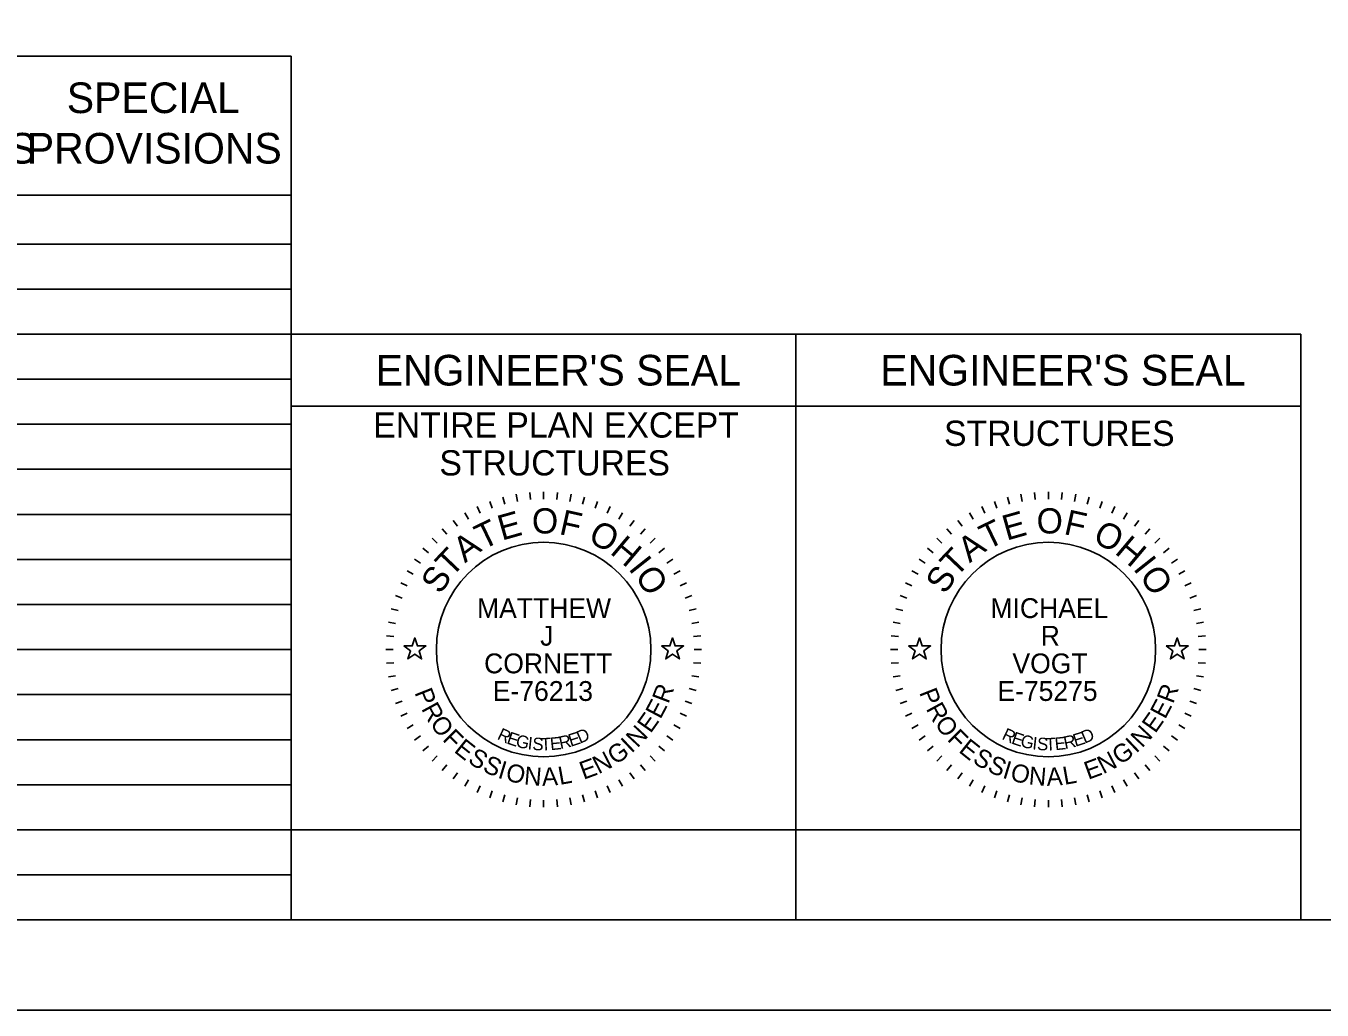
# Model space of a CAD drawing. Extents: x 0 to 34, y 0 to 22.
# Drawn here: x 22.13 to 29.32, y 0 to 5.46 of the extents above; entities that cross this region are included whole.
import ezdxf

# ---------------------------------------------------------------- set-up
doc = ezdxf.new("R2010")
doc.units = 0
for name, color, linetype in [('GM_X_State_Route', 7, 'Continuous'), ('SH_Border', 7, 'Continuous'), ('SH_Cut_Line', 7, 'Continuous'), ('SH_Data', 7, 'Continuous'), ('SH_Text', 7, 'Continuous')]:
    doc.layers.add(name, color=color, linetype=linetype)

msp = doc.modelspace()

# ---------------------------------------------------------------- linework, layer by layer
at = {"layer": 'GM_X_State_Route'}
for p, q in [((24.7007, 2.8222), (24.7144, 2.7846)), ((24.7735, 2.8452), (24.7839, 2.8065)), ((24.8481, 2.8617), (24.855, 2.8223)), ((24.9237, 2.8717), (24.9272, 2.8318)), ((25, 2.875), (25, 2.835)), ((25.0763, 2.8717), (25.0728, 2.8318)), ((25.1519, 2.8617), (25.145, 2.8223)), ((25.2265, 2.8452), (25.2161, 2.8065)), ((25.2993, 2.8222), (25.2856, 2.7846)), ((27.5007, 2.8222), (27.5144, 2.7846)), ((27.5735, 2.8452), (27.5839, 2.8065)), ((27.6481, 2.8617), (27.655, 2.8223)), ((27.7237, 2.8717), (27.7272, 2.8318)), ((27.8, 2.875), (27.8, 2.835)), ((27.8763, 2.8717), (27.8728, 2.8318)), ((27.9519, 2.8617), (27.945, 2.8223)), ((28.0265, 2.8452), (28.0161, 2.8065)), ((28.0993, 2.8222), (28.0856, 2.7846)), ((24.5625, 2.7578), (24.5825, 2.7231)), ((24.6302, 2.793), (24.6471, 2.7568)), ((25.3698, 2.793), (25.3529, 2.7568)), ((25.4375, 2.7578), (25.4175, 2.7231)), ((27.3625, 2.7578), (27.3825, 2.7231)), ((27.4302, 2.793), (27.4471, 2.7568)), ((28.1698, 2.793), (28.1529, 2.7568)), ((28.2375, 2.7578), (28.2175, 2.7231)), ((24.4376, 2.6703), (24.4633, 2.6396)), ((24.4981, 2.7168), (24.5211, 2.684)), ((25.5019, 2.7168), (25.4789, 2.684)), ((25.5624, 2.6703), (25.5367, 2.6396)), ((27.2376, 2.6703), (27.2633, 2.6396)), ((27.2981, 2.7168), (27.3211, 2.684)), ((28.3019, 2.7168), (28.2789, 2.684)), ((28.3624, 2.6703), (28.3367, 2.6396)), ((24.3813, 2.6187), (24.4096, 2.5904)), ((25.6187, 2.6187), (25.5904, 2.5904)), ((27.1813, 2.6187), (27.2096, 2.5904)), ((28.4187, 2.6187), (28.3904, 2.5904)), ((24.3297, 2.5624), (24.3604, 2.5367)), ((25.6703, 2.5624), (25.6396, 2.5367)), ((27.1297, 2.5624), (27.1604, 2.5367)), ((28.4703, 2.5624), (28.4396, 2.5367)), ((24.2832, 2.5019), (24.316, 2.4789)), ((25.7168, 2.5019), (25.684, 2.4789)), ((27.0832, 2.5019), (27.116, 2.4789)), ((28.5168, 2.5019), (28.484, 2.4789)), ((24.2422, 2.4375), (24.2769, 2.4175)), ((25.7578, 2.4375), (25.7231, 2.4175)), ((27.0422, 2.4375), (27.0769, 2.4175)), ((28.5578, 2.4375), (28.5231, 2.4175)), ((24.207, 2.3698), (24.2432, 2.3529)), ((25.793, 2.3698), (25.7568, 2.3529)), ((27.007, 2.3698), (27.0432, 2.3529)), ((28.593, 2.3698), (28.5568, 2.3529)), ((24.1778, 2.2993), (24.2154, 2.2856)), ((25.8222, 2.2993), (25.7846, 2.2856)), ((26.9778, 2.2993), (27.0154, 2.2856)), ((28.6222, 2.2993), (28.5846, 2.2856)), ((24.1548, 2.2265), (24.1935, 2.2161)), ((25.8452, 2.2265), (25.8065, 2.2161)), ((26.9548, 2.2265), (26.9935, 2.2161)), ((28.6452, 2.2265), (28.6065, 2.2161)), ((24.1383, 2.1519), (24.1777, 2.145)), ((25.8617, 2.1519), (25.8223, 2.145)), ((26.9383, 2.1519), (26.9777, 2.145)), ((28.6617, 2.1519), (28.6223, 2.145)), ((24.1283, 2.0763), (24.1682, 2.0728)), ((25.8717, 2.0763), (25.8318, 2.0728)), ((26.9283, 2.0763), (26.9682, 2.0728)), ((28.6717, 2.0763), (28.6318, 2.0728)), ((24.125, 2), (24.165, 2)), ((25.875, 2), (25.835, 2)), ((26.925, 2), (26.965, 2)), ((28.675, 2), (28.635, 2)), ((24.1283, 1.9237), (24.1682, 1.9272)), ((25.8717, 1.9237), (25.8318, 1.9272)), ((26.9283, 1.9237), (26.9682, 1.9272)), ((28.6717, 1.9237), (28.6318, 1.9272)), ((24.1383, 1.8481), (24.1777, 1.855)), ((25.8617, 1.8481), (25.8223, 1.855)), ((26.9383, 1.8481), (26.9777, 1.855)), ((28.6617, 1.8481), (28.6223, 1.855)), ((24.1548, 1.7735), (24.1935, 1.7839)), ((25.8452, 1.7735), (25.8065, 1.7839)), ((26.9548, 1.7735), (26.9935, 1.7839)), ((28.6452, 1.7735), (28.6065, 1.7839)), ((24.1778, 1.7007), (24.2154, 1.7144)), ((25.8222, 1.7007), (25.7846, 1.7144)), ((26.9778, 1.7007), (27.0154, 1.7144)), ((28.6222, 1.7007), (28.5846, 1.7144)), ((24.207, 1.6302), (24.2432, 1.6471)), ((24.2422, 1.5625), (24.2769, 1.5825)), ((25.7578, 1.5625), (25.7231, 1.5825)), ((25.793, 1.6302), (25.7568, 1.6471)), ((27.007, 1.6302), (27.0432, 1.6471)), ((27.0422, 1.5625), (27.0769, 1.5825)), ((28.5578, 1.5625), (28.5231, 1.5825)), ((28.593, 1.6302), (28.5568, 1.6471)), ((24.2832, 1.4981), (24.316, 1.5211)), ((25.7168, 1.4981), (25.684, 1.5211)), ((27.0832, 1.4981), (27.116, 1.5211)), ((28.5168, 1.4981), (28.484, 1.5211)), ((24.3297, 1.4376), (24.3604, 1.4633)), ((25.6703, 1.4376), (25.6396, 1.4633)), ((27.1297, 1.4376), (27.1604, 1.4633)), ((28.4703, 1.4376), (28.4396, 1.4633)), ((24.3813, 1.3813), (24.4096, 1.4096)), ((25.6187, 1.3813), (25.5904, 1.4096)), ((27.1813, 1.3813), (27.2096, 1.4096)), ((28.4187, 1.3813), (28.3904, 1.4096)), ((24.4376, 1.3297), (24.4633, 1.3604)), ((24.4981, 1.2832), (24.5211, 1.316)), ((25.5019, 1.2832), (25.4789, 1.316)), ((25.5624, 1.3297), (25.5367, 1.3604)), ((27.2376, 1.3297), (27.2633, 1.3604)), ((27.2981, 1.2832), (27.3211, 1.316)), ((28.3019, 1.2832), (28.2789, 1.316)), ((28.3624, 1.3297), (28.3367, 1.3604)), ((24.5625, 1.2422), (24.5825, 1.2769)), ((24.6302, 1.207), (24.6471, 1.2432)), ((25.3698, 1.207), (25.3529, 1.2432)), ((25.4375, 1.2422), (25.4175, 1.2769)), ((27.3625, 1.2422), (27.3825, 1.2769)), ((27.4302, 1.207), (27.4471, 1.2432)), ((28.1698, 1.207), (28.1529, 1.2432)), ((28.2375, 1.2422), (28.2175, 1.2769)), ((24.7007, 1.1778), (24.7144, 1.2154)), ((24.7735, 1.1548), (24.7839, 1.1935)), ((24.8481, 1.1383), (24.855, 1.1777)), ((24.9237, 1.1283), (24.9272, 1.1682)), ((25, 1.125), (25, 1.165)), ((25.0763, 1.1283), (25.0728, 1.1682)), ((25.1519, 1.1383), (25.145, 1.1777)), ((25.2265, 1.1548), (25.2161, 1.1935)), ((25.2993, 1.1778), (25.2856, 1.2154)), ((27.5007, 1.1778), (27.5144, 1.2154)), ((27.5735, 1.1548), (27.5839, 1.1935)), ((27.6481, 1.1383), (27.655, 1.1777)), ((27.7237, 1.1283), (27.7272, 1.1682)), ((27.8, 1.125), (27.8, 1.165)), ((27.8763, 1.1283), (27.8728, 1.1682)), ((27.9519, 1.1383), (27.945, 1.1777)), ((28.0265, 1.1548), (28.0161, 1.1935)), ((28.0993, 1.1778), (28.0856, 1.2154))]:
    msp.add_line(p, q, dxfattribs=at)
for points in [[(24.2236, 2.02), (24.2705, 2.02), (24.285, 2.0645), (24.2995, 2.02), (24.3464, 2.02), (24.3085, 1.9924), (24.323, 1.9478), (24.285, 1.9754), (24.247, 1.9478), (24.2615, 1.9924)], [(25.6536, 2.02), (25.7005, 2.02), (25.715, 2.0645), (25.7295, 2.02), (25.7764, 2.02), (25.7385, 1.9924), (25.753, 1.9478), (25.715, 1.9754), (25.677, 1.9478), (25.6915, 1.9924)], [(27.0236, 2.02), (27.0705, 2.02), (27.085, 2.0645), (27.0995, 2.02), (27.1464, 2.02), (27.1085, 1.9924), (27.123, 1.9478), (27.085, 1.9754), (27.047, 1.9478), (27.0615, 1.9924)], [(28.4536, 2.02), (28.5005, 2.02), (28.515, 2.0645), (28.5295, 2.02), (28.5764, 2.02), (28.5385, 1.9924), (28.553, 1.9478), (28.515, 1.9754), (28.477, 1.9478), (28.4915, 1.9924)]]:
    msp.add_lwpolyline(points, close=True, dxfattribs=at)
for centre in [(25, 2), (27.8, 2)]:
    msp.add_circle(centre, 0.595, dxfattribs=at)
at = {"layer": 'SH_Cut_Line'}
for p, q in [((10.15, 5.2918), (23.6, 5.2918)), ((23.6, 0.5), (23.6, 5.2918)), ((10.15, 4.5209), (23.6, 4.5209)), ((10.15, 4.25), (23.6, 4.25)), ((10.15, 4), (23.6, 4)), ((10.15, 3.75), (23.6, 3.75)), ((23.6, 0.5), (23.6, 3.75)), ((23.6, 3.75), (26.4, 3.75)), ((26.4, 0.5), (26.4, 3.75)), ((26.4, 0.5), (26.4, 3.75)), ((26.4, 3.75), (29.2, 3.75)), ((26.4, 3.75), (26.4, 0.5)), ((29.2, 3.75), (29.2, 0.5)), ((10.15, 3.5), (23.6, 3.5)), ((23.6, 3.35), (26.4, 3.35)), ((26.4, 3.35), (29.2, 3.35)), ((10.15, 3.25), (23.6, 3.25)), ((10.15, 3), (23.6, 3)), ((10.15, 2.75), (23.6, 2.75)), ((10.15, 2.5), (23.6, 2.5)), ((10.15, 2.25), (23.6, 2.25)), ((10.15, 2), (23.6, 2)), ((10.15, 1.75), (23.6, 1.75)), ((10.15, 1.5), (23.6, 1.5)), ((10.15, 1.25), (23.6, 1.25)), ((10.15, 1), (23.6, 1)), ((10.15, 0.75), (23.6, 0.75)), ((23.6, 0.5), (26.4, 0.5)), ((26.4, 0.5), (29.2, 0.5))]:
    msp.add_line(p, q, dxfattribs=at)
for points in [[(23.6, 0.5), (23.6, 1), (26.4, 1), (26.4, 0.5)], [(26.4, 0.5), (26.4, 1), (29.2, 1), (29.2, 0.5)]]:
    msp.add_lwpolyline(points, close=True, dxfattribs=at)
at = {"layer": 'SH_Data'}
msp.add_lwpolyline([(1.5, 21.5), (33.5, 21.5), (33.5, 0.5), (1.5, 0.5)], close=True, dxfattribs=at)
at = {"layer": 'SH_Text'}
msp.add_lwpolyline([(0, 0), (34, 0), (34, 22), (0, 22)], close=True, dxfattribs=at)

# ---------------------------------------------------------------- texts
at = {"layer": 'GM_X_State_Route'}
for s, height, rotation, p in [('E', 0.14, 15.75706, (24.7684, 2.6038)), ('O', 0.14, 359.78119, (24.9347, 2.6443)), ('F', 0.14, 347.43619, (25.0811, 2.6417)), ('E', 0.14, 15.75706, (27.5684, 2.6038)), ('O', 0.14, 359.78119, (27.7347, 2.6443)), ('F', 0.14, 347.43619, (27.8811, 2.6417)), ('T', 0.14, 25.71674, (24.6616, 2.5518)), ('O', 0.14, 332.25863, (25.2398, 2.6015)), ('T', 0.14, 25.71674, (27.4616, 2.5518)), ('O', 0.14, 332.25863, (28.0398, 2.6015)), ('A', 0.14, 36.47472, (24.5634, 2.4781)), ('H', 0.14, 319.91363, (25.3632, 2.5361)), ('A', 0.14, 36.47472, (27.3634, 2.4781)), ('H', 0.14, 319.91363, (28.1632, 2.5361)), ('T', 0.14, 46.4344, (24.4883, 2.3964)), ('I', 0.14, 308.36695, (25.4665, 2.4483)), ('T', 0.14, 46.4344, (27.2883, 2.3964)), ('I', 0.14, 308.36695, (28.2665, 2.4483)), ('S', 0.14, 57.19238, (24.4281, 2.3014)), ('O', 0.14, 303.14906, (25.5021, 2.4089)), ('S', 0.14, 57.19238, (27.2281, 2.3014)), ('O', 0.14, 303.14906, (28.3021, 2.4089)), ('R', 0.1, 69.23216, (25.6919, 1.6954)), ('R', 0.1, 69.23216, (28.4919, 1.6954)), ('P', 0.1, 291.49398, (24.2823, 1.7621)), ('E', 0.1, 61.99508, (25.6476, 1.6098)), ('P', 0.1, 291.49398, (27.0823, 1.7621)), ('E', 0.1, 61.99508, (28.4476, 1.6098)), ('R', 0.1, 298.73106, (24.319, 1.6717)), ('E', 0.1, 54.75801, (25.5933, 1.5314)), ('R', 0.1, 298.73106, (27.119, 1.6717)), ('E', 0.1, 54.75801, (28.3933, 1.5314)), ('O', 0.1, 306.46664, (24.3655, 1.5883)), ('O', 0.1, 306.46664, (27.1655, 1.5883)), ('F', 0.1, 314.7068, (24.4343, 1.4983)), ('R', 0.07, 334.48695, (24.7375, 1.5051)), ('E', 0.07, 341.03996, (24.7906, 1.4801)), ('G', 0.07, 347.47515, (24.8414, 1.4618)), ('I', 0.07, 353.78581, (24.9091, 1.4468)), ('S', 0.07, 356.89262, (24.9358, 1.4429)), ('T', 0.07, 3.00609, (24.9857, 1.4387)), ('E', 0.07, 6.01169, (25.0389, 1.4412)), ('R', 0.07, 11.91844, (25.0925, 1.4474)), ('E', 0.07, 17.68363, (25.1498, 1.4602)), ('D', 0.07, 23.30524, (25.201, 1.477)), ('I', 0.1, 43.28703, (25.4868, 1.4214)), ('N', 0.1, 47.02243, (25.5202, 1.4508)), ('F', 0.1, 314.7068, (27.2343, 1.4983)), ('R', 0.07, 334.48695, (27.5375, 1.5051)), ('E', 0.07, 341.03996, (27.5906, 1.4801)), ('G', 0.07, 347.47515, (27.6414, 1.4618)), ('I', 0.07, 353.78581, (27.7091, 1.4468)), ('S', 0.07, 356.89262, (27.7358, 1.4429)), ('T', 0.07, 3.00609, (27.7857, 1.4387)), ('E', 0.07, 6.01169, (27.8389, 1.4412)), ('R', 0.07, 11.91844, (27.8925, 1.4474)), ('E', 0.07, 17.68363, (27.9498, 1.4602)), ('D', 0.07, 23.30524, (28.001, 1.477)), ('I', 0.1, 43.28703, (28.2868, 1.4214)), ('N', 0.1, 47.02243, (28.3202, 1.4508)), ('E', 0.1, 321.43929, (24.4978, 1.4348)), ('S', 0.1, 328.67637, (24.5743, 1.3752)), ('G', 0.1, 35.04687, (25.3981, 1.357)), ('E', 0.1, 321.43929, (27.2978, 1.4348)), ('S', 0.1, 328.67637, (27.3743, 1.3752)), ('G', 0.1, 35.04687, (28.1981, 1.357)), ('S', 0.1, 335.91345, (24.6564, 1.3266)), ('I', 0.1, 343.15053, (24.7406, 1.2897)), ('O', 0.1, 346.88592, (24.7839, 1.2751)), ('E', 0.1, 20.07421, (25.2212, 1.277)), ('N', 0.1, 27.31129, (25.3045, 1.3075)), ('S', 0.1, 335.91345, (27.4564, 1.3266)), ('I', 0.1, 343.15053, (27.5406, 1.2897)), ('O', 0.1, 346.88592, (27.5839, 1.2751)), ('E', 0.1, 20.07421, (28.0212, 1.277)), ('N', 0.1, 27.31129, (28.1045, 1.3075)), ('N', 0.1, 355.12608, (24.8888, 1.2517)), ('A', 0.1, 2.86166, (24.9923, 1.2437)), ('L', 0.1, 10.09874, (25.0894, 1.249)), ('N', 0.1, 355.12608, (27.6888, 1.2517)), ('A', 0.1, 2.86166, (27.7923, 1.2437)), ('L', 0.1, 10.09874, (27.8894, 1.249))]:
    msp.add_text(s, height=height, rotation=rotation, dxfattribs=at).set_placement(p)
for s, p in [('MATTHEW', (24.6304, 2.1749)), ('MICHAEL', (27.4789, 2.1749)), ('J', (24.9808, 2.0216)), ('R', (27.7577, 2.0216)), ('CORNETT', (24.6696, 1.8684)), ('VOGT', (27.6009, 1.8684)), ('E-76213', (24.7177, 1.7151)), ('E-75275', (27.5173, 1.7151))]:
    msp.add_text(s, height=0.11, dxfattribs=at).set_placement(p)
at = {"layer": 'SH_Border'}
for s, p in [('SPECIAL', (22.3542, 4.9763)), ('SPECIFICATIONS', (20.2871, 4.6963)), ('PROVISIONS', (22.1323, 4.6963))]:
    msp.add_text(s, height=0.17, dxfattribs=at).set_placement(p)
at = {"layer": 'SH_Cut_Line'}
for s, height, p in [("ENGINEER'S SEAL", 0.17, (24.0676, 3.465)), ("ENGINEER'S SEAL", 0.17, (26.8676, 3.465)), ('ENTIRE PLAN EXCEPT', 0.14, (24.0545, 3.1759)), ('STRUCTURES', 0.14, (27.2215, 3.13)), ('STRUCTURES', 0.14, (24.4215, 2.9659))]:
    msp.add_text(s, height=height, dxfattribs=at).set_placement(p)

doc.saveas('drawing.dxf')
